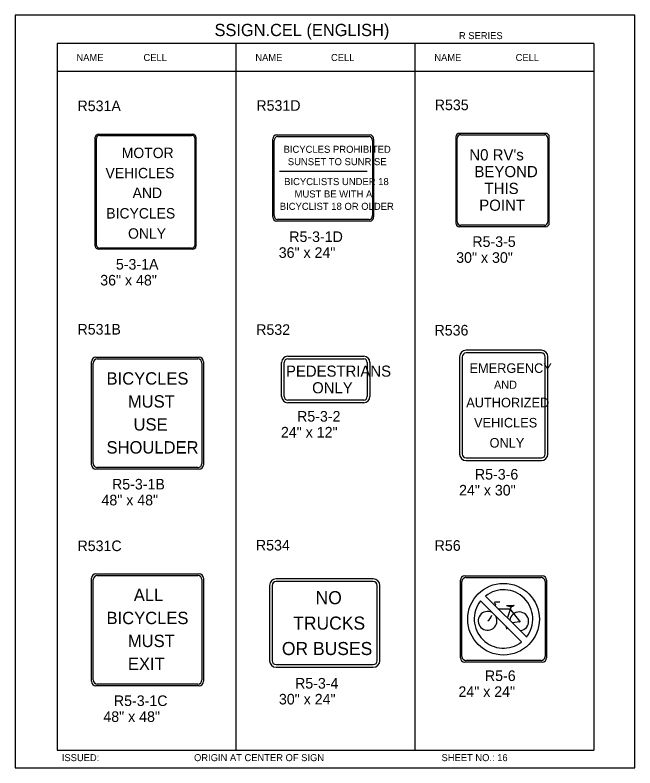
# Model space of a CAD drawing. Extents: x -5299 to 22597, y -19549 to -1808.
# Drawn here: x -2827 to -2126, y -5466 to -4614 of the extents above; entities that cross this region are included whole.
import ezdxf

# ---------------------------------------------------------------- set-up
doc = ezdxf.new("R2010")
doc.units = 0
for name, color, linetype in [('Level 1', 7, 'Continuous'), ('Level 2', 7, 'Continuous'), ('Level 3', 7, 'Continuous'), ('Level 63', 7, 'Continuous')]:
    doc.layers.add(name, color=color, linetype=linetype)

msp = doc.modelspace()

# ---------------------------------------------------------------- linework, layer by layer
at = {"layer": 'Level 1'}
for p, q in [((-2172.62, -4645.77), (-2779.63, -4645.77)), ((-2779.63, -4645.77), (-2779.63, -5445.77)), ((-2577.29, -4645.77), (-2577.29, -5445.77)), ((-2374.95, -4645.77), (-2374.95, -5445.77)), ((-2172.62, -4645.77), (-2172.62, -5445.77)), ((-2172.62, -4677.44), (-2779.63, -4677.44)), ((-2734.97, -4874.4), (-2734.97, -4752.79)), ((-2731.46, -4749.78), (-2627.5, -4749.78)), ((-2623.99, -4752.79), (-2623.99, -4874.4)), ((-2534.03, -4840.55), (-2534.03, -4755.66)), ((-2530.52, -4751.15), (-2426.56, -4751.15)), ((-2423.05, -4755.66), (-2423.05, -4840.55)), ((-2327.04, -4847.68), (-2327.04, -4752.97)), ((-2323.13, -4749.06), (-2228.42, -4749.06)), ((-2224.51, -4752.97), (-2224.51, -4847.68)), ((-2527.99, -4790.47), (-2428.86, -4790.47)), ((-2478.54, -4798.11), (-2478.54, -4798.11)), ((-2275.78, -4800.32), (-2275.78, -4800.32)), ((-2679.48, -4813.6), (-2679.48, -4813.6)), ((-2426.56, -4845.06), (-2530.52, -4845.06)), ((-2228.42, -4851.59), (-2323.13, -4851.59)), ((-2627.5, -4877.41), (-2731.46, -4877.41)), ((-2734.12, -5002.91), (-2620.48, -5002.91)), ((-2734.12, -5002.91), (-2734.12, -5002.91)), ((-2518.76, -5002.82), (-2432.85, -5002.82)), ((-2321.44, -5000.56), (-2321.44, -5110.54)), ((-2231.93, -4996.16), (-2317.04, -4996.16)), ((-2227.53, -5110.54), (-2227.53, -5000.56)), ((-2738.82, -5121.25), (-2738.82, -5007.6)), ((-2615.79, -5007.6), (-2615.79, -5121.25)), ((-2522.76, -5045.44), (-2522.76, -5006.82)), ((-2428.85, -5006.82), (-2428.85, -5045.44)), ((-2475.8, -5026.13), (-2475.8, -5026.13)), ((-2432.85, -5049.44), (-2518.76, -5049.44)), ((-2274.49, -5055.55), (-2274.49, -5055.55)), ((-2677.3, -5064.43), (-2677.3, -5064.43)), ((-2317.04, -5114.94), (-2231.93, -5114.94)), ((-2620.48, -5125.94), (-2734.12, -5125.94)), ((-2734.12, -5248.06), (-2620.48, -5248.06)), ((-2317.17, -5250.38), (-2232.28, -5250.38)), ((-2738.82, -5366.39), (-2738.82, -5252.75)), ((-2615.79, -5252.75), (-2615.79, -5366.39)), ((-2421.98, -5255.01), (-2531.96, -5255.01)), ((-2321.68, -5339.78), (-2321.68, -5254.89)), ((-2227.77, -5254.89), (-2227.77, -5339.78)), ((-2536.36, -5259.41), (-2536.36, -5344.52)), ((-2417.58, -5344.52), (-2417.58, -5259.41)), ((-2295.11, -5271.32), (-2248.72, -5317.71)), ((-2300.67, -5276.89), (-2254.28, -5323.28)), ((-2284.99, -5279.54), (-2283.67, -5277.96)), ((-2283.29, -5280.93), (-2284.87, -5279.48)), ((-2284.17, -5282.26), (-2283.29, -5280.87)), ((-2283.67, -5277.96), (-2278.87, -5277.96)), ((-2271.34, -5282.01), (-2262.62, -5281.56)), ((-2266.1, -5283.08), (-2270.27, -5295.72)), ((-2280.63, -5285.73), (-2267.17, -5285.73)), ((-2256.3, -5299.7), (-2267.05, -5285.8)), ((-2274.72, -5297.33), (-2274.72, -5297.33)), ((-2256.55, -5300.46), (-2264.58, -5301.66)), ((-2677.3, -5309.57), (-2677.3, -5309.57)), ((-2476.97, -5301.97), (-2476.97, -5301.97)), ((-2271.72, -5308.23), (-2270.52, -5308.23)), ((-2271.15, -5308.17), (-2271.6, -5305.96)), ((-2232.28, -5344.29), (-2317.17, -5344.29)), ((-2531.96, -5348.92), (-2421.98, -5348.92)), ((-2620.48, -5371.08), (-2734.12, -5371.08)), ((-2779.63, -5445.77), (-2172.62, -5445.77))]:
    msp.add_line(p, q, dxfattribs=at)
msp.add_circle((-2274.7, -5297.56), 40.55, dxfattribs=at)
for centre, radius, start, end in [((-2323.13, -4752.97), 3.91, 90, 180), ((-2228.42, -4752.97), 3.91, 0, 90), ((-2323.13, -4847.68), 3.91, 180, 270), ((-2228.42, -4847.68), 3.91, 270, 0), ((-2734.12, -5007.6), 4.69, 90, 180), ((-2620.48, -5007.6), 4.69, 0, 90), ((-2518.76, -5006.82), 4, 90, 180), ((-2432.85, -5006.82), 4, 0, 90), ((-2317.04, -5000.56), 4.4, 90, 180), ((-2231.93, -5000.56), 4.4, 0, 90), ((-2518.76, -5045.44), 4, 180, 270), ((-2432.85, -5045.44), 4, 270, 0), ((-2317.04, -5110.54), 4.4, 180, 270), ((-2231.93, -5110.54), 4.4, 270, 0), ((-2734.12, -5121.25), 4.69, 180, 270), ((-2620.48, -5121.25), 4.69, 270, 0), ((-2734.12, -5252.75), 4.69, 90, 180), ((-2317.17, -5254.89), 4.51, 90, 180), ((-2232.28, -5254.89), 4.51, 0, 90), ((-2531.96, -5259.41), 4.4, 90, 180), ((-2421.98, -5259.41), 4.4, 0, 90), ((-2274.68, -5297.28), 33.06, 321.76775, 128.23225), ((-2274.73, -5297.33), 33.06, 141.74129, 308.25871), ((-2266.72, -5273.52), 9.64, 241.41615, 272.9372), ((-2265.97, -5278.76), 4.36, 266.77433, 320.07562), ((-2292.74, -5299.43), 10.63, 61.76879, 28.23121), ((-2299.94, -5288.97), 12.8, 305.49778, 341.05407), ((-2256.96, -5299.99), 10.63, 276.97454, 173.93712), ((-2256.39, -5300.05), 0.409, 243.59031, 74.49814), ((-2317.17, -5339.78), 4.51, 180, 270), ((-2232.28, -5339.78), 4.51, 270, 0), ((-2531.96, -5344.52), 4.4, 180, 270), ((-2421.98, -5344.52), 4.4, 270, 0), ((-2734.12, -5366.39), 4.69, 180, 270), ((-2620.48, -5366.39), 4.69, 270, 0)]:
    msp.add_arc(centre, radius, start, end, dxfattribs=at)
for centre, major_axis, ratio, start_param, end_param in [((-2731.46, -4752.79), (-3.51, 0), 0.857082, 4.712389, 6.283185), ((-2627.5, -4752.79), (-3.51, 0), 0.857082, 3.141593, 4.712389), ((-2530.52, -4755.66), (0, -4.51), 0.777833, 3.141593, 4.712389), ((-2426.56, -4755.66), (0, 4.51), 0.777833, 4.712389, 6.283185), ((-2530.52, -4840.55), (0, -4.51), 0.777833, 4.712389, 6.283185), ((-2426.56, -4840.55), (0, 4.51), 0.777833, 3.141593, 4.712389), ((-2731.46, -4874.4), (3.51, 0), 0.857082, 3.141593, 4.712389), ((-2627.5, -4874.4), (3.51, 0), 0.857082, 4.712389, 6.283185)]:
    msp.add_ellipse(centre, major_axis=major_axis, ratio=ratio, start_param=start_param, end_param=end_param, dxfattribs=at)
at = {"layer": 'Level 3'}
for p, q in [((-2227.17, -4747.49), (-2324.38, -4747.49)), ((-2736.38, -4875.37), (-2736.38, -4751.83)), ((-2732.59, -4748.57), (-2626.38, -4748.57)), ((-2622.58, -4751.83), (-2622.58, -4875.37)), ((-2535.44, -4841.99), (-2535.44, -4754.22)), ((-2531.65, -4749.34), (-2425.44, -4749.34)), ((-2421.65, -4754.22), (-2421.65, -4841.99)), ((-2328.61, -4751.72), (-2328.61, -4848.93)), ((-2222.95, -4848.93), (-2222.95, -4751.72)), ((-2425.44, -4846.87), (-2531.65, -4846.87)), ((-2324.38, -4853.15), (-2227.17, -4853.15)), ((-2626.38, -4878.62), (-2732.59, -4878.62)), ((-2231.93, -4993.16), (-2317.04, -4993.16)), ((-2735.63, -5001.03), (-2618.98, -5001.03)), ((-2518.76, -4999.82), (-2432.85, -4999.82)), ((-2324.44, -5000.56), (-2324.44, -5110.54)), ((-2224.53, -5110.54), (-2224.53, -5000.56)), ((-2740.7, -5122.75), (-2740.7, -5006.1)), ((-2613.91, -5006.1), (-2613.91, -5122.75)), ((-2525.76, -5045.44), (-2525.76, -5006.82)), ((-2425.85, -5006.82), (-2425.85, -5045.44)), ((-2432.85, -5052.44), (-2518.76, -5052.44)), ((-2317.04, -5117.94), (-2231.93, -5117.94)), ((-2618.98, -5127.82), (-2735.63, -5127.82)), ((-2735.63, -5246.18), (-2618.98, -5246.18)), ((-2318.61, -5248.57), (-2230.84, -5248.57)), ((-2740.7, -5367.89), (-2740.7, -5251.25)), ((-2613.91, -5251.25), (-2613.91, -5367.89)), ((-2421.98, -5252.01), (-2531.96, -5252.01)), ((-2323.49, -5341.22), (-2323.49, -5253.45)), ((-2225.96, -5253.45), (-2225.96, -5341.22)), ((-2539.36, -5259.41), (-2539.36, -5344.52)), ((-2414.58, -5344.52), (-2414.58, -5259.41)), ((-2531.96, -5351.92), (-2421.98, -5351.92)), ((-2230.84, -5346.1), (-2318.61, -5346.1)), ((-2618.98, -5372.97), (-2735.63, -5372.97))]:
    msp.add_line(p, q, dxfattribs=at)
for centre, radius, start, end in [((-2324.38, -4751.72), 4.23, 90, 180), ((-2227.17, -4751.72), 4.23, 0, 90), ((-2324.38, -4848.93), 4.23, 180, 270), ((-2227.17, -4848.93), 4.23, 270, 0), ((-2317.04, -5000.56), 7.4, 90, 180), ((-2231.93, -5000.56), 7.4, 0, 90), ((-2735.63, -5006.1), 5.07, 90, 180), ((-2618.98, -5006.1), 5.07, 0, 90), ((-2518.76, -5006.82), 7, 90, 180), ((-2432.85, -5006.82), 7, 0, 90), ((-2518.76, -5045.44), 7, 180, 270), ((-2432.85, -5045.44), 7, 270, 0), ((-2317.04, -5110.54), 7.4, 180, 270), ((-2231.93, -5110.54), 7.4, 270, 0), ((-2735.63, -5122.75), 5.07, 180, 270), ((-2618.98, -5122.75), 5.07, 270, 0), ((-2735.63, -5251.25), 5.07, 90, 180), ((-2620.48, -5252.75), 4.69, 0, 90), ((-2618.98, -5251.25), 5.07, 0, 90), ((-2318.61, -5253.45), 4.88, 90, 180), ((-2230.84, -5253.45), 4.88, 0, 90), ((-2531.96, -5259.41), 7.4, 90, 180), ((-2421.98, -5259.41), 7.4, 0, 90), ((-2318.61, -5341.22), 4.88, 180, 270), ((-2230.84, -5341.22), 4.88, 270, 0), ((-2531.96, -5344.52), 7.4, 180, 270), ((-2421.98, -5344.52), 7.4, 270, 0), ((-2735.63, -5367.89), 5.07, 180, 270), ((-2618.98, -5367.89), 5.07, 270, 0)]:
    msp.add_arc(centre, radius, start, end, dxfattribs=at)
for centre, major_axis, ratio, start_param, end_param in [((-2732.59, -4751.83), (-3.79, 0), 0.857082, 4.712389, 6.283185), ((-2626.38, -4751.83), (-3.79, 0), 0.857082, 3.141593, 4.712389), ((-2531.65, -4754.22), (0, -4.88), 0.777833, 3.141593, 4.712389), ((-2425.44, -4754.22), (0, 4.88), 0.777833, 4.712389, 6.283185), ((-2531.65, -4841.99), (0, -4.88), 0.777833, 4.712389, 6.283185), ((-2425.44, -4841.99), (0, 4.88), 0.777833, 3.141593, 4.712389), ((-2732.59, -4875.37), (3.79, 0), 0.857082, 3.141593, 4.712389), ((-2626.38, -4875.37), (3.79, 0), 0.857082, 4.712389, 6.283185)]:
    msp.add_ellipse(centre, major_axis=major_axis, ratio=ratio, start_param=start_param, end_param=end_param, dxfattribs=at)
at = {"layer": 'Level 63'}
msp.add_lwpolyline([(-2827.14, -5465.96), (-2126.09, -5465.96), (-2126.09, -4613.58), (-2827.14, -4613.58)], close=True, dxfattribs=at)

# ---------------------------------------------------------------- texts
at = {"layer": 'Level 1'}
for s, height, p in [('MOTOR', 11.785, (-2706.46, -4775.52)), ('BICYCLES PROHIBITED', 8, (-2523.51, -4769.54)), ("N0 RV's", 12.679, (-2313.42, -4778.14)), ('SUNSET TO SUNRISE', 8, (-2518.69, -4783.54)), ('VEHICLES', 11.785, (-2724.85, -4798.37)), ('BEYOND', 12.679, (-2307.62, -4797.15)), ('BICYCLISTS UNDER 18', 8, (-2522.84, -4806.11)), ('THIS', 12.679, (-2296.26, -4816.17)), ('AND', 11.785, (-2694.19, -4820.77)), ('MUST BE WITH A', 8, (-2511.05, -4820.11)), ('POINT', 12.679, (-2302.19, -4835.19)), ('BICYCLES', 11.785, (-2723.97, -4843.91)), ('BICYCLIST 18 OR OLDER', 8, (-2527.77, -4834.12)), ('ONLY', 11.785, (-2699.35, -4866.78)), ('PEDESTRIANS', 12.5897, (-2520.72, -5022.98)), ('EMERGENCY', 10.8, (-2313.16, -5018.72)), ('BICYCLES', 14, (-2723.66, -5031.99)), ('AND', 9.2, (-2285.46, -5036.74)), ('ONLY', 12.59, (-2491.16, -5041.86)), ('MUST', 14, (-2699.55, -5057.99)), ('AUTHORIZED', 10.8, (-2316.88, -5057.68)), ('USE', 14, (-2693.16, -5083.99)), ('VEHICLES', 10.8, (-2308.04, -5080.48)), ('SHOULDER', 14, (-2723.71, -5109.99)), ('ONLY', 10.8, (-2290.51, -5103.28)), ('ALL', 14, (-2692.87, -5277.14)), ('NO', 14.8, (-2487.25, -5280.57)), ('BICYCLES', 14, (-2723.66, -5303.14)), ('TRUCKS', 14.8, (-2512.6, -5309.37)), ('MUST', 14, (-2699.55, -5329.14)), ('OR BUSES', 14.8, (-2525.4, -5338.17)), ('EXIT', 14, (-2699.55, -5355.14))]:
    msp.add_text(s, height=height, dxfattribs=at).set_placement(p)
at = {"layer": 'Level 2'}
for s, p in [('R531A', (-2756.55, -4722.37)), ('R531D', (-2554.24, -4721.97)), ('R535', (-2352.5, -4721.28)), ('R5-3-1D', (-2517.03, -4870.49)), ('R5-3-5', (-2309.97, -4876.11)), ('36" x 24"', (-2528.94, -4888.49)), ('30" x 30"', (-2328.2, -4894.11)), ('5-3-1A', (-2713.1, -4901.74)), ('36" x 48"', (-2730.81, -4919.74)), ('R531B', (-2756.55, -4975.33)), ('R532', (-2554.45, -4975.67)), ('R536', (-2352.77, -4976.38)), ('R5-3-6', (-2307.08, -5139.5)), ('24" x 30"', (-2324.99, -5157.5)), ('R534', (-2554.74, -5219.78)), ('R56', (-2352.61, -5220.13)), ('R531C', (-2756.55, -5220.47)), ('R5-6', (-2295.77, -5367.55)), ('R5-3-4', (-2510.48, -5376.1)), ('24" x 24"', (-2325.68, -5385.55)), ('30" x 24"', (-2528.72, -5394.1))]:
    msp.add_text(s, height=12, dxfattribs=at).set_placement(p)
at = {"layer": 'Level 3'}
for s, height, p in [('SSIGN.CEL (ENGLISH)', 13.8566, (-2601.56, -4637.38)), ('R SERIES', 7.918, (-2325.12, -4640.82)), ('NAME', 7.918, (-2757.76, -4665.6)), ('CELL', 7.918, (-2681.9, -4665.6)), ('NAME', 7.918, (-2555.39, -4665.6)), ('CELL', 7.918, (-2469.83, -4665.6)), ('NAME', 7.918, (-2353, -4665.6)), ('CELL', 7.918, (-2261, -4665.6)), ('R5-3-2', 12, (-2508.21, -5073.85)), ('24" x 12"', 12, (-2526.44, -5091.85)), ('R5-3-1B', 12, (-2717.5, -5150.71)), ('48" x 48"', 12, (-2729.4, -5168.71)), ('R5-3-1C', 12, (-2715.38, -5395.86)), ('48" x 48"', 12, (-2727.29, -5413.86)), ('ISSUED:', 7.918, (-2774.27, -5458.26)), ('ORIGIN AT CENTER OF SIGN', 7.9181, (-2624.73, -5458.26)), ('SHEET NO.: 16', 7.918, (-2344.8, -5458.26))]:
    msp.add_text(s, height=height, dxfattribs=at).set_placement(p)

doc.saveas('drawing.dxf')
